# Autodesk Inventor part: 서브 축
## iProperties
Created: 2013-12
Part Number: 서브 축
Material: Steel
Document SubType Name: Modeling
Designer: 한국산업디자인학원
Categories: <?xml version="1.0" encoding="UTF-16"?> <MemberInstance><Categories><FamilyTemplate><FamilyTemplateParameter ValueType="xs:double" Id="1" ObjectReferenceKey="da
Density: 1 g/cm^3
CustomPartVersion: 1
Author: 한국산업디자인학원
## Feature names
1. Extrusion1
